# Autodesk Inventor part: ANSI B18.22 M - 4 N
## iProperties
Comments: To add or edit properties for Autodesk Inventor files, use iProperties.
Created: 2004-08
Part Number: ANSI B18.22 M - 4 N
Vendor: Autodesk Inc.
Document SubType Name: Modeling
Designer: John Blackburn
Material: Default
Description: Plain Washer
Standard: ANSI B18.22 M
Size Designation: 4 N
Alert: To add or edit properties for Autodesk Inventor files, use iProperties.
Control State: 0
Master: False
Checked Out: False
Shininess: 64.0
Length Units: 11269
Angle Units: 11279
Time Units: 11290
Mass Units: 11283
Length Display Precision: 3
Angle Display Precision: 2
Compacted: True
Classification: un/spsc 31161807
Density: 0.0
Volumn: 0.0
Area: 0.0
PropertySet Name: Model Information
Author: John Blackburn
Revision Number: 8
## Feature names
1. Body [Extrusion]
